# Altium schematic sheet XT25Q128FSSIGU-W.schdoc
size 127 x 101 mm
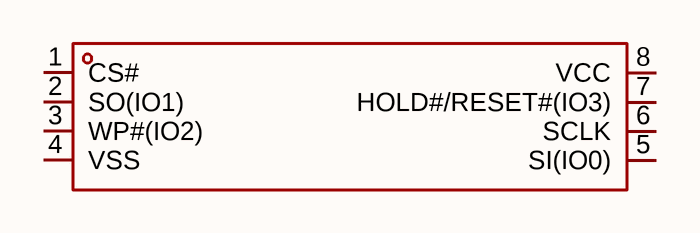
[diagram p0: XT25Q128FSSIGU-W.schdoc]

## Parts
U?  xt25q128fssigu-w  [SOP-8_L5.3-W5.2-P1.27-LS7.9-BL]  (value not drawn)

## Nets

Not connected (* = marked no-connect by the designer): U? 1(CS#) 2(SO(IO1)) 3(WP#(IO2)) 4(VSS) 5(SI(IO0)) 6(SCLK) 7(HOLD#/RESET#(IO3)) 8(VCC)

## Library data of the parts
U? = xt25q128fssigu-w: 接口类型:SPI;存储容量:128Mbit;时钟频率(fc):104MHz;; Manufacturer: XTX(芯天下); AddInBom: yes; ModelId: b3bace262c53465a9e6115a2e0c7b3cc; ModelTransform: 205.905,311.023,0,0,0,0,0,0,0; Interface: SPI; Clock Frequency: 104MHz; Voltage - Supply: 1.7V~2V; Standby Supply Current: 5uA; Program / Erase Cycles: 100000次; Page Programming Time (Tpp): 350us; Block Erase Time(tBE): 120ms@(32KB); Data Retention - TDR (Year): 20年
